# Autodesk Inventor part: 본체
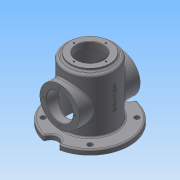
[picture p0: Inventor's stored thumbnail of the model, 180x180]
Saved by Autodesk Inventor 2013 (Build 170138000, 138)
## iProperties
Created: 2018-04
Part Number: 본체
Material: 일반
Document SubType Name: Modeling
Designer: Administrator
Density: 1 g/cm^3
Author: Administrator
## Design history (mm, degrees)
sketch "스케치1"
  geometry: L1 (0, 0)-(50, 0); L2 (50, 0)-(50, 8); L3 (50, 8)-(80, 8); L4 (80, 8)-(80, 18); L5 (80, 18)-(50, 18); L6 (50, 18)-(50, 128); L7 (50, 128)-(40, 128); L8 (40, 128)-(40, 133); L9 (40, 133)-(0, 133); L10 (0, 133)-(0, 0)
  constraints: 20 end point, 6 parallel, 2 collinear, 2 perpendicular, 1 horizontal
  dimensions: "d9" = 100 diameter of L6 L10; "d12" = 160 diameter of L4 L10; "d13" = 80 diameter of L8 L10; "d14" = 10 distance between parallel lines of L3 L5; "d15" = 8 distance between parallel lines of L1 L3; "d16" = 125 distance between parallel lines of L3 L9; "d17" = 110 distance between parallel lines of L5 L7
revolve "회전1" sketch "스케치1" stored, may be unused: angle "d18" = 90 deg
hole "구멍1" diameter "d21" = 54; stored, may be unused: countersink angle "d25" = 90 deg, drill point angle "d27" = 118 deg; dims "d19" = 10, "d20" = 10, "d22" = 6, "d23" = 90, "d24" = 120, "d26" = 8
sketch "스케치2"
  geometry: C1 r 27 at (0, 0) reference; 1 further point
  constraints: 1 vertical alignment
  dimensions: "d28" = 32.5 distance of C1.centre point (0, 32.5)
hole "구멍2" sketch "스케치2" at (0, 32.5) diameter "d29" = 3.242; stored, may be unused: countersink angle "d33" = 90 deg, drill point angle "d35" = 118 deg; dims "d30" = 8, "d31" = 90, "d32" = 120, "d34" = 10
node "작업 평면1"
sketch "스케치3"
  geometry: L1 (8, 80)-(8, -80) reference; C1 r 40 at (68, 0); 1 further point
  constraints: 1 centre point, 1 horizontal alignment
  dimensions: "d40" = 80 diameter of C1; "d41" = 60 distance from line of C1.centre L1
extrude "돌출1" join sketch "스케치3" stored distance "d42" = 10; taper "d43" = 0 deg
hole "구멍3" diameter "d46" = 54; stored, may be unused: countersink angle "d50" = 90 deg, drill point angle "d52" = 118 deg; dims "d44" = 10, "d45" = 10, "d47" = 8, "d48" = 90, "d49" = 120, "d51" = 10
sketch "스케치4"
  geometry: C1 r 27 at (0, 0) reference; 2 further points
  constraints: 1 vertical alignment
  dimensions: "d53" = 32.5 distance of C1.centre point (0, 32.5)
hole "구멍4" sketch "스케치4" at (0, 32.5) diameter "d54" = 3.242; stored, may be unused: countersink angle "d58" = 90 deg, drill point angle "d60" = 118 deg; dims "d55" = 8, "d56" = 90, "d57" = 120, "d59" = 10
sketch "스케치5"
  geometry: L1 (0, 0)-(-67.5, 0); L2 (0, 0)-(-47.73, 47.73); C1 r 50 at (0, 0) reference; A1 r 67.5 centre (0, 0) between (-67.5, 0) and (-47.73, 47.73); 1 further point
  constraints: 4 end point, 2 coincident, 2 point on circle, 1 centre point, 1 horizontal
  dimensions: "d64" = 135 diameter of A1; "d65" = 45 deg angle of L1 L2
hole "구멍5" sketch "스케치5" at (-47.73, 47.73) diameter "d67" = 10; stored, may be unused: countersink angle "d71" = 90 deg, drill point angle "d73" = 118 deg; dims "d68" = 8, "d69" = 90, "d70" = 120, "d72" = 10
sketch "스케치6"
  geometry: L1 (0, 0)-(-80, 0); C1 r 50 at (0, 0) reference; C2 r 15 at (-80, 0); 1 further point
  constraints: 2 end point, 1 centre point, 1 coincident, 1 horizontal, 1 horizontal alignment, 1 other
  dimensions: "d77" = 30 diameter of C2
extrude "돌출2" cut sketch "스케치6" stored distance "d78" = 10; taper "d79" = 0 deg
node "작업 평면2"
sketch "스케치7"
  geometry: L1 (-78.594, 8)-(78.594, 8) reference; 2 further points
  constraints: 1 vertical alignment, 1 other
  dimensions: "d81" = 70 distance from line of L1 point (0, 78)
feature "엠보싱1" sketch "스케치7" dims "d9" = 100, "d12" = 160, "d13" = 80, "d14" = 10, "d15" = 8, "d16" = 125, "d17" = 110, "d82" = 0.5, "d83" = 0
fillet "모깎기1" dims "d84" = 3
fillet "모깎기2" dims "d85" = 5
fillet "모깎기3" dims "d86" = 3
fillet "모깎기4" dims "d87" = 3
chamfer "모따기1" distance "d88" = 1; stored, may be unused: second distance "d89" = 2, angle "d90" = 45 deg
fillet "모깎기5" dims "d91" = 3
node "솔리드1"
pattern_circular "원형 패턴1" dims angle "d37" = 360 deg
mirror "대칭1"
pattern_circular "원형 패턴2" dims angle "d62" = 360 deg
mirror "대칭2"
pattern_circular "원형 패턴3" dims angle "d75" = 360 deg
mirror "대칭3"
other parameters: "d39" = 62, "d80" = 130.25
